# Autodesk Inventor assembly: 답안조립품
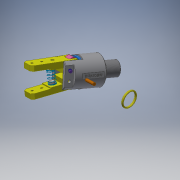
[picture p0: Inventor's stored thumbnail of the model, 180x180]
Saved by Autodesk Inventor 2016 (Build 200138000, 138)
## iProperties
Created: 2019-02
Part Number: 답안조립품
Material: 일반
Document SubType Name: Assembly
Designer: USER
Author: USER
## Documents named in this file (11)
- C:\Users\USER\Desktop\490207V1011\답안조립품.iam
- C:\Users\USER\Desktop\490207V1011\본체.ipt
- C:\Users\USER\Desktop\490207V1011\E-링.ipt
- C:\Users\USER\Desktop\490207V1011\O-링.ipt
- C:\Users\USER\Desktop\490207V1011\가이드핀.ipt
- C:\Users\USER\Desktop\490207V1011\부시.ipt
- C:\Users\USER\Desktop\490207V1011\스프링.ipt
- C:\Users\USER\Desktop\490207V1011\평행핀 6x28.ipt
- C:\Users\USER\Desktop\490207V1011\피스톤.ipt
- C:\Users\USER\Desktop\490207V1011\핀.ipt
- C:\Users\USER\Desktop\490207V1011\핑거.ipt
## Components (9 placed, 6 different names)
1. E-링:1
2. O-링:1
3. 가이드핀:1
4. 피스톤:1 — 플러쉬:1
5. 핀:1
6. 핑거:2
7. 핑거:3
8. 가이드핀:2
9. E-링:2
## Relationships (1: Flush 1)
- 플러쉬:1 [Flush]: 피스톤:1
